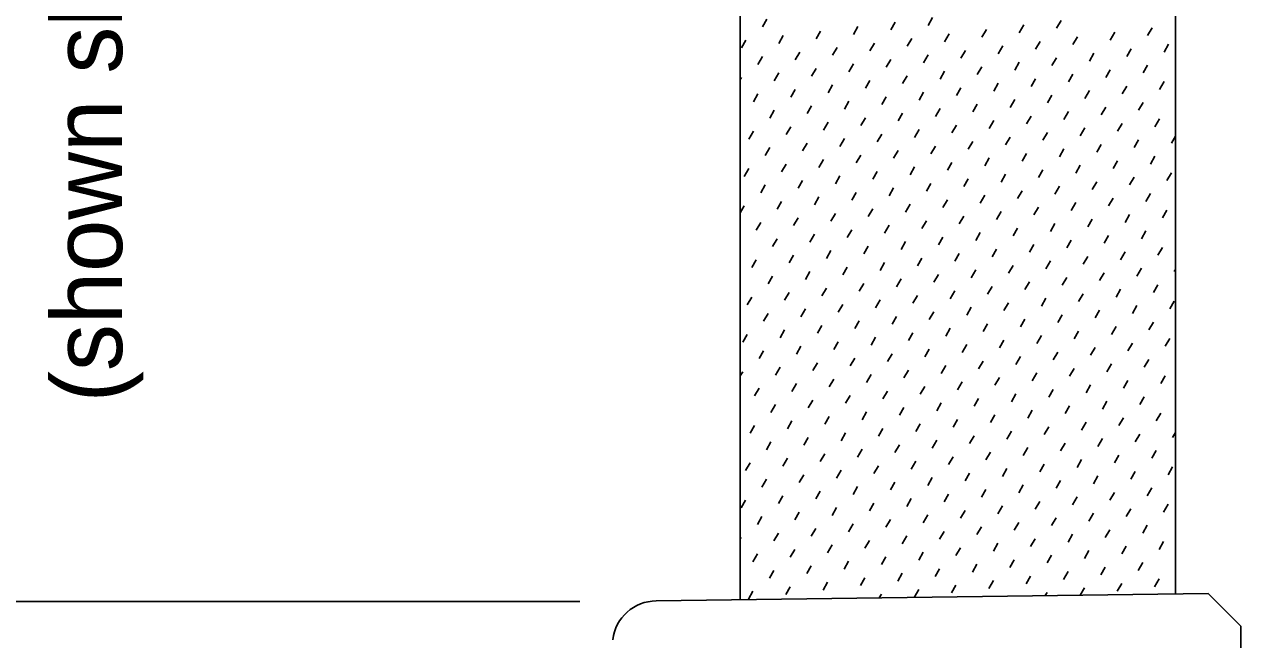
# Model space of a CAD drawing. Extents: x 21629.5 to 21698.8, y 56199.4 to 56237.6.
# Drawn here: x 21644.187 to 21647.681, y 56214.672 to 56216.439 of the extents above; entities that cross this region are included whole.
import ezdxf

# ---------------------------------------------------------------- set-up
doc = ezdxf.new("R2010")
doc.units = 0
for name, color, linetype in [('Dimension', 7, 'Continuous'), ('ExistSuperStruct', 7, 'Continuous'), ('Miscellaneous', 7, 'Continuous')]:
    doc.layers.add(name, color=color, linetype=linetype)

msp = doc.modelspace()

# ---------------------------------------------------------------- linework, layer by layer
at = {"layer": 'Dimension'}
msp.add_line((21645.7831, 56214.7815), (21643.3116, 56214.7815), dxfattribs=at)
at = {"layer": 'ExistSuperStruct'}
for p, q in [((21647.494, 56217.7505), (21647.494, 56214.8034)), ((21646.244, 56214.7863), (21646.244, 56216.5317)), ((21646.0026, 56214.783), (21647.5877, 56214.8047)), ((21647.6815, 56214.711), (21647.5877, 56214.8047)), ((21647.6815, 56212.8767), (21647.6815, 56214.711))]:
    msp.add_line(p, q, dxfattribs=at)
msp.add_arc((21646.0026, 56214.658), 0.125, 90, 173.6598, dxfattribs=at)
at = {"layer": 'Miscellaneous'}
for p, q in [((21646.3075, 56216.4312), (21646.3205, 56216.4536)), ((21646.5691, 56216.41), (21646.5821, 56216.4324)), ((21646.6764, 56216.4229), (21646.6893, 56216.4453)), ((21646.7836, 56216.4359), (21646.7966, 56216.4583)), ((21647.0452, 56216.4147), (21647.0582, 56216.4371)), ((21647.1525, 56216.4276), (21647.1654, 56216.45)), ((21647.4141, 56216.4064), (21647.4271, 56216.4288)), ((21646.2474, 56216.3711), (21646.2603, 56216.3935)), ((21646.3546, 56216.384), (21646.3676, 56216.4064)), ((21646.4619, 56216.397), (21646.4748, 56216.4194)), ((21646.7235, 56216.3758), (21646.7365, 56216.3982)), ((21646.8307, 56216.3888), (21646.8437, 56216.4111)), ((21646.938, 56216.4017), (21646.951, 56216.4241)), ((21647.1996, 56216.3805), (21647.2126, 56216.4029)), ((21647.3069, 56216.3935), (21647.3198, 56216.4159)), ((21646.4018, 56216.3369), (21646.4147, 56216.3593)), ((21646.509, 56216.3499), (21646.522, 56216.3723)), ((21646.6163, 56216.3628), (21646.6292, 56216.3852)), ((21646.8779, 56216.3416), (21646.8909, 56216.364)), ((21646.9851, 56216.3546), (21646.9981, 56216.377)), ((21647.0924, 56216.3675), (21647.1053, 56216.3899)), ((21647.354, 56216.3463), (21647.367, 56216.3687)), ((21647.4613, 56216.3593), (21647.4742, 56216.3817)), ((21646.2945, 56216.3239), (21646.3075, 56216.3463)), ((21646.5562, 56216.3027), (21646.5691, 56216.3251)), ((21646.6634, 56216.3157), (21646.6764, 56216.3381)), ((21646.7706, 56216.3287), (21646.7836, 56216.351)), ((21647.0323, 56216.3074), (21647.0452, 56216.3298)), ((21647.1395, 56216.3204), (21647.1525, 56216.3428)), ((21647.2468, 56216.3334), (21647.2597, 56216.3558)), ((21646.3417, 56216.2768), (21646.3546, 56216.2992)), ((21646.4489, 56216.2898), (21646.4619, 56216.3122)), ((21646.7105, 56216.2685), (21646.7235, 56216.2909)), ((21646.8178, 56216.2815), (21646.8307, 56216.3039)), ((21646.925, 56216.2945), (21646.938, 56216.3169)), ((21647.1867, 56216.2733), (21647.1996, 56216.2957)), ((21647.2939, 56216.2862), (21647.3069, 56216.3086)), ((21647.4011, 56216.2992), (21647.4141, 56216.3216)), ((21646.244, 56216.2804), (21646.2474, 56216.2862)), ((21646.3888, 56216.2297), (21646.4018, 56216.252)), ((21646.4961, 56216.2426), (21646.509, 56216.265)), ((21646.6033, 56216.2556), (21646.6163, 56216.278)), ((21646.8649, 56216.2344), (21646.8779, 56216.2568)), ((21646.9722, 56216.2473), (21646.9851, 56216.2697)), ((21647.0794, 56216.2603), (21647.0924, 56216.2827)), ((21647.341, 56216.2391), (21647.354, 56216.2615)), ((21647.4483, 56216.252), (21647.4613, 56216.2744)), ((21646.2816, 56216.2167), (21646.2945, 56216.2391)), ((21646.5432, 56216.1955), (21646.5562, 56216.2179)), ((21646.6504, 56216.2084), (21646.6634, 56216.2308)), ((21646.7577, 56216.2214), (21646.7706, 56216.2438)), ((21647.0193, 56216.2002), (21647.0323, 56216.2226)), ((21647.1266, 56216.2132), (21647.1395, 56216.2355)), ((21647.2338, 56216.2261), (21647.2468, 56216.2485)), ((21646.3287, 56216.1696), (21646.3417, 56216.1919)), ((21646.4359, 56216.1825), (21646.4489, 56216.2049)), ((21646.6976, 56216.1613), (21646.7105, 56216.1837)), ((21646.8048, 56216.1743), (21646.8178, 56216.1967)), ((21646.9121, 56216.1872), (21646.925, 56216.2096)), ((21647.1737, 56216.166), (21647.1867, 56216.1884)), ((21647.2809, 56216.179), (21647.2939, 56216.2014)), ((21647.3882, 56216.1919), (21647.4011, 56216.2143)), ((21646.4831, 56216.1354), (21646.4961, 56216.1578)), ((21646.5903, 56216.1483), (21646.6033, 56216.1707)), ((21646.852, 56216.1271), (21646.8649, 56216.1495)), ((21646.9592, 56216.1401), (21646.9722, 56216.1625)), ((21647.0665, 56216.1531), (21647.0794, 56216.1754)), ((21647.3281, 56216.1318), (21647.341, 56216.1542)), ((21647.4353, 56216.1448), (21647.4483, 56216.1672)), ((21646.2686, 56216.1094), (21646.2816, 56216.1318)), ((21646.3758, 56216.1224), (21646.3888, 56216.1448)), ((21646.6375, 56216.1012), (21646.6504, 56216.1236)), ((21646.7447, 56216.1142), (21646.7577, 56216.1366)), ((21647.0063, 56216.0929), (21647.0193, 56216.1153)), ((21647.1136, 56216.1059), (21647.1266, 56216.1283)), ((21647.2208, 56216.1189), (21647.2338, 56216.1413)), ((21647.4825, 56216.0977), (21647.494, 56216.1176)), ((21646.3157, 56216.0623), (21646.3287, 56216.0847)), ((21646.423, 56216.0753), (21646.4359, 56216.0977)), ((21646.5302, 56216.0882), (21646.5432, 56216.1106)), ((21646.7919, 56216.067), (21646.8048, 56216.0894)), ((21646.8991, 56216.08), (21646.9121, 56216.1024)), ((21647.1607, 56216.0588), (21647.1737, 56216.0812)), ((21647.268, 56216.0717), (21647.2809, 56216.0941)), ((21647.3752, 56216.0847), (21647.3882, 56216.1071)), ((21646.4701, 56216.0281), (21646.4831, 56216.0505)), ((21646.5774, 56216.0411), (21646.5903, 56216.0635)), ((21646.6846, 56216.0541), (21646.6976, 56216.0765)), ((21646.839, 56216.0199), (21646.852, 56216.0423)), ((21646.9462, 56216.0328), (21646.9592, 56216.0552)), ((21647.0535, 56216.0458), (21647.0665, 56216.0682)), ((21647.3151, 56216.0246), (21647.3281, 56216.047)), ((21647.4224, 56216.0376), (21647.4353, 56216.06)), ((21646.2556, 56216.0022), (21646.2686, 56216.0246)), ((21646.3629, 56216.0152), (21646.3758, 56216.0376)), ((21646.6245, 56215.994), (21646.6375, 56216.0163)), ((21646.7318, 56216.0069), (21646.7447, 56216.0293)), ((21646.9934, 56215.9857), (21647.0063, 56216.0081)), ((21647.1006, 56215.9987), (21647.1136, 56216.0211)), ((21647.2079, 56216.0116), (21647.2208, 56216.034)), ((21647.4695, 56215.9904), (21647.4825, 56216.0128)), ((21646.3028, 56215.9551), (21646.3157, 56215.9775)), ((21646.41, 56215.968), (21646.423, 56215.9904)), ((21646.5173, 56215.981), (21646.5302, 56216.0034)), ((21646.7789, 56215.9598), (21646.7919, 56215.9822)), ((21646.8861, 56215.9727), (21646.8991, 56215.9951)), ((21647.1478, 56215.9515), (21647.1607, 56215.9739)), ((21647.255, 56215.9645), (21647.268, 56215.9869)), ((21647.3623, 56215.9775), (21647.3752, 56215.9998)), ((21646.4572, 56215.9209), (21646.4701, 56215.9433)), ((21646.5644, 56215.9339), (21646.5774, 56215.9562)), ((21646.6716, 56215.9468), (21646.6846, 56215.9692)), ((21646.9333, 56215.9256), (21646.9462, 56215.948)), ((21647.0405, 56215.9386), (21647.0535, 56215.961)), ((21647.3022, 56215.9174), (21647.3151, 56215.9397)), ((21647.4094, 56215.9303), (21647.4224, 56215.9527)), ((21646.244, 56215.8973), (21646.2556, 56215.9174)), ((21646.3499, 56215.9079), (21646.3629, 56215.9303)), ((21646.6115, 56215.8867), (21646.6245, 56215.9091)), ((21646.7188, 56215.8997), (21646.7318, 56215.9221)), ((21646.826, 56215.9126), (21646.839, 56215.935)), ((21647.0877, 56215.8914), (21647.1006, 56215.9138)), ((21647.1949, 56215.9044), (21647.2079, 56215.9268)), ((21647.4565, 56215.8832), (21647.4695, 56215.9056)), ((21646.2898, 56215.8478), (21646.3028, 56215.8702)), ((21646.3971, 56215.8608), (21646.41, 56215.8832)), ((21646.5043, 56215.8737), (21646.5173, 56215.8961)), ((21646.7659, 56215.8525), (21646.7789, 56215.8749)), ((21646.8732, 56215.8655), (21646.8861, 56215.8879)), ((21646.9804, 56215.8785), (21646.9934, 56215.9009)), ((21647.242, 56215.8572), (21647.255, 56215.8796)), ((21647.3493, 56215.8702), (21647.3623, 56215.8926)), ((21646.4442, 56215.8136), (21646.4572, 56215.836)), ((21646.5514, 56215.8266), (21646.5644, 56215.849)), ((21646.6587, 56215.8396), (21646.6716, 56215.862)), ((21646.9203, 56215.8184), (21646.9333, 56215.8407)), ((21647.0276, 56215.8313), (21647.0405, 56215.8537)), ((21647.1348, 56215.8443), (21647.1478, 56215.8667)), ((21647.2892, 56215.8101), (21647.3022, 56215.8325)), ((21647.3964, 56215.8231), (21647.4094, 56215.8455)), ((21646.337, 56215.8007), (21646.3499, 56215.8231)), ((21646.5986, 56215.7795), (21646.6115, 56215.8019)), ((21646.7058, 56215.7924), (21646.7188, 56215.8148)), ((21646.8131, 56215.8054), (21646.826, 56215.8278)), ((21647.0747, 56215.7842), (21647.0877, 56215.8066)), ((21647.1819, 56215.7971), (21647.1949, 56215.8195)), ((21647.4436, 56215.7759), (21647.4565, 56215.7983)), ((21646.2768, 56215.7406), (21646.2898, 56215.763)), ((21646.3841, 56215.7535), (21646.3971, 56215.7759)), ((21646.4913, 56215.7665), (21646.5043, 56215.7889)), ((21646.753, 56215.7453), (21646.7659, 56215.7677)), ((21646.8602, 56215.7583), (21646.8732, 56215.7806)), ((21646.9675, 56215.7712), (21646.9804, 56215.7936)), ((21647.2291, 56215.75), (21647.242, 56215.7724)), ((21647.3363, 56215.763), (21647.3493, 56215.7854)), ((21646.4312, 56215.7064), (21646.4442, 56215.7288)), ((21646.5385, 56215.7194), (21646.5514, 56215.7418)), ((21646.6457, 56215.7323), (21646.6587, 56215.7547)), ((21646.9074, 56215.7111), (21646.9203, 56215.7335)), ((21647.0146, 56215.7241), (21647.0276, 56215.7465)), ((21647.1218, 56215.737), (21647.1348, 56215.7594)), ((21647.3835, 56215.7158), (21647.3964, 56215.7382)), ((21647.4907, 56215.7288), (21647.494, 56215.7345)), ((21646.324, 56215.6934), (21646.337, 56215.7158)), ((21646.5856, 56215.6722), (21646.5986, 56215.6946)), ((21646.6929, 56215.6852), (21646.7058, 56215.7076)), ((21646.8001, 56215.6981), (21646.8131, 56215.7205)), ((21647.0617, 56215.6769), (21647.0747, 56215.6993)), ((21647.169, 56215.6899), (21647.1819, 56215.7123)), ((21647.2762, 56215.7029), (21647.2892, 56215.7253)), ((21646.3711, 56215.6463), (21646.3841, 56215.6687)), ((21646.4784, 56215.6593), (21646.4913, 56215.6816)), ((21646.74, 56215.638), (21646.753, 56215.6604)), ((21646.8472, 56215.651), (21646.8602, 56215.6734)), ((21646.9545, 56215.664), (21646.9675, 56215.6864)), ((21647.2161, 56215.6428), (21647.2291, 56215.6651)), ((21647.3234, 56215.6557), (21647.3363, 56215.6781)), ((21647.4306, 56215.6687), (21647.4436, 56215.6911)), ((21646.2639, 56215.6333), (21646.2768, 56215.6557)), ((21646.5255, 56215.6121), (21646.5385, 56215.6345)), ((21646.6328, 56215.6251), (21646.6457, 56215.6475)), ((21646.8944, 56215.6039), (21646.9074, 56215.6263)), ((21647.0016, 56215.6168), (21647.0146, 56215.6392)), ((21647.1089, 56215.6298), (21647.1218, 56215.6522)), ((21647.3705, 56215.6086), (21647.3835, 56215.631)), ((21647.4778, 56215.6215), (21647.4907, 56215.6439)), ((21646.311, 56215.5862), (21646.324, 56215.6086)), ((21646.4183, 56215.5992), (21646.4312, 56215.6215)), ((21646.6799, 56215.5779), (21646.6929, 56215.6003)), ((21646.7871, 56215.5909), (21646.8001, 56215.6133)), ((21647.0488, 56215.5697), (21647.0617, 56215.5921)), ((21647.156, 56215.5827), (21647.169, 56215.605)), ((21647.2633, 56215.5956), (21647.2762, 56215.618)), ((21646.3582, 56215.539), (21646.3711, 56215.5614)), ((21646.4654, 56215.552), (21646.4784, 56215.5744)), ((21646.5727, 56215.565), (21646.5856, 56215.5874)), ((21646.727, 56215.5308), (21646.74, 56215.5532)), ((21646.8343, 56215.5438), (21646.8472, 56215.5662)), ((21646.9415, 56215.5567), (21646.9545, 56215.5791)), ((21647.2032, 56215.5355), (21647.2161, 56215.5579)), ((21647.3104, 56215.5485), (21647.3234, 56215.5709)), ((21647.4176, 56215.5614), (21647.4306, 56215.5838)), ((21646.2509, 56215.5261), (21646.2639, 56215.5485)), ((21646.5125, 56215.5049), (21646.5255, 56215.5273)), ((21646.6198, 56215.5178), (21646.6328, 56215.5402)), ((21646.8814, 56215.4966), (21646.8944, 56215.519)), ((21646.9887, 56215.5096), (21647.0016, 56215.532)), ((21647.0959, 56215.5225), (21647.1089, 56215.5449)), ((21647.3575, 56215.5013), (21647.3705, 56215.5237)), ((21647.4648, 56215.5143), (21647.4778, 56215.5367)), ((21646.2981, 56215.4789), (21646.311, 56215.5013)), ((21646.4053, 56215.4919), (21646.4183, 56215.5143)), ((21646.6669, 56215.4707), (21646.6799, 56215.4931)), ((21646.7742, 56215.4837), (21646.7871, 56215.5061)), ((21647.0358, 56215.4624), (21647.0488, 56215.4848)), ((21647.1431, 56215.4754), (21647.156, 56215.4978)), ((21647.2503, 56215.4884), (21647.2633, 56215.5108)), ((21646.3452, 56215.4318), (21646.3582, 56215.4542)), ((21646.4524, 56215.4448), (21646.4654, 56215.4672)), ((21646.5597, 56215.4577), (21646.5727, 56215.4801)), ((21646.8213, 56215.4365), (21646.8343, 56215.4589)), ((21646.9286, 56215.4495), (21646.9415, 56215.4719)), ((21647.1902, 56215.4283), (21647.2032, 56215.4507)), ((21647.2974, 56215.4412), (21647.3104, 56215.4636)), ((21647.4047, 56215.4542), (21647.4176, 56215.4766)), ((21646.244, 56215.4293), (21646.2509, 56215.4412)), ((21646.4996, 56215.3976), (21646.5125, 56215.42)), ((21646.6068, 56215.4106), (21646.6198, 56215.433)), ((21646.7141, 56215.4236), (21646.727, 56215.4459)), ((21646.9757, 56215.4023), (21646.9887, 56215.4247)), ((21647.0829, 56215.4153), (21647.0959, 56215.4377)), ((21647.3446, 56215.3941), (21647.3575, 56215.4165)), ((21647.4518, 56215.4071), (21647.4648, 56215.4294)), ((21646.2851, 56215.3717), (21646.2981, 56215.3941)), ((21646.3923, 56215.3847), (21646.4053, 56215.4071)), ((21646.654, 56215.3635), (21646.6669, 56215.3858)), ((21646.7612, 56215.3764), (21646.7742, 56215.3988)), ((21646.8685, 56215.3894), (21646.8814, 56215.4118)), ((21647.1301, 56215.3682), (21647.1431, 56215.3906)), ((21647.2373, 56215.3811), (21647.2503, 56215.4035)), ((21646.3322, 56215.3246), (21646.3452, 56215.347)), ((21646.4395, 56215.3375), (21646.4524, 56215.3599)), ((21646.5467, 56215.3505), (21646.5597, 56215.3729)), ((21646.8084, 56215.3293), (21646.8213, 56215.3517)), ((21646.9156, 56215.3422), (21646.9286, 56215.3646)), ((21647.0228, 56215.3552), (21647.0358, 56215.3776)), ((21647.1772, 56215.321), (21647.1902, 56215.3434)), ((21647.2845, 56215.334), (21647.2974, 56215.3564)), ((21647.3917, 56215.347), (21647.4047, 56215.3693)), ((21646.4866, 56215.2904), (21646.4996, 56215.3128)), ((21646.5939, 56215.3033), (21646.6068, 56215.3257)), ((21646.7011, 56215.3163), (21646.7141, 56215.3387)), ((21646.9627, 56215.2951), (21646.9757, 56215.3175)), ((21647.07, 56215.3081), (21647.0829, 56215.3305)), ((21647.3316, 56215.2868), (21647.3446, 56215.3092)), ((21647.4389, 56215.2998), (21647.4518, 56215.3222)), ((21646.2721, 56215.2645), (21646.2851, 56215.2868)), ((21646.3794, 56215.2774), (21646.3923, 56215.2998)), ((21646.641, 56215.2562), (21646.654, 56215.2786)), ((21646.7483, 56215.2692), (21646.7612, 56215.2916)), ((21646.8555, 56215.2821), (21646.8685, 56215.3045)), ((21647.1171, 56215.2609), (21647.1301, 56215.2833)), ((21647.2244, 56215.2739), (21647.2373, 56215.2963)), ((21646.3193, 56215.2173), (21646.3322, 56215.2397)), ((21646.4265, 56215.2303), (21646.4395, 56215.2527)), ((21646.5338, 56215.2432), (21646.5467, 56215.2656)), ((21646.7954, 56215.222), (21646.8084, 56215.2444)), ((21646.9026, 56215.235), (21646.9156, 56215.2574)), ((21647.0099, 56215.248), (21647.0228, 56215.2703)), ((21647.2715, 56215.2267), (21647.2845, 56215.2491)), ((21647.3788, 56215.2397), (21647.3917, 56215.2621)), ((21647.486, 56215.2527), (21647.494, 56215.2665)), ((21646.4737, 56215.1831), (21646.4866, 56215.2055)), ((21646.5809, 56215.1961), (21646.5939, 56215.2185)), ((21646.6881, 56215.2091), (21646.7011, 56215.2315)), ((21646.9498, 56215.1879), (21646.9627, 56215.2102)), ((21647.057, 56215.2008), (21647.07, 56215.2232)), ((21647.1643, 56215.2138), (21647.1772, 56215.2362)), ((21647.4259, 56215.1926), (21647.4389, 56215.215)), ((21646.2592, 56215.1572), (21646.2721, 56215.1796)), ((21646.3664, 56215.1702), (21646.3794, 56215.1926)), ((21646.628, 56215.149), (21646.641, 56215.1714)), ((21646.7353, 56215.1619), (21646.7483, 56215.1843)), ((21646.8425, 56215.1749), (21646.8555, 56215.1973)), ((21647.1042, 56215.1537), (21647.1171, 56215.1761)), ((21647.2114, 56215.1666), (21647.2244, 56215.189)), ((21647.3187, 56215.1796), (21647.3316, 56215.202)), ((21646.4136, 56215.123), (21646.4265, 56215.1454)), ((21646.5208, 56215.136), (21646.5338, 56215.1584)), ((21646.7824, 56215.1148), (21646.7954, 56215.1372)), ((21646.8897, 56215.1277), (21646.9026, 56215.1501)), ((21646.9969, 56215.1407), (21647.0099, 56215.1631)), ((21647.2585, 56215.1195), (21647.2715, 56215.1419)), ((21647.3658, 56215.1325), (21647.3788, 56215.1549)), ((21647.473, 56215.1454), (21647.486, 56215.1678)), ((21646.3063, 56215.1101), (21646.3193, 56215.1325)), ((21646.5679, 56215.0889), (21646.5809, 56215.1112)), ((21646.6752, 56215.1018), (21646.6881, 56215.1242)), ((21646.9368, 56215.0806), (21646.9498, 56215.103)), ((21647.0441, 56215.0936), (21647.057, 56215.116)), ((21647.1513, 56215.1065), (21647.1643, 56215.1289)), ((21647.4129, 56215.0853), (21647.4259, 56215.1077)), ((21646.2462, 56215.05), (21646.2592, 56215.0724)), ((21646.3535, 56215.0629), (21646.3664, 56215.0853)), ((21646.4607, 56215.0759), (21646.4737, 56215.0983)), ((21646.6151, 56215.0417), (21646.628, 56215.0641)), ((21646.7223, 56215.0547), (21646.7353, 56215.0771)), ((21646.8296, 56215.0676), (21646.8425, 56215.09)), ((21647.0912, 56215.0464), (21647.1042, 56215.0688)), ((21647.1984, 56215.0594), (21647.2114, 56215.0818)), ((21647.3057, 56215.0724), (21647.3187, 56215.0948)), ((21646.4006, 56215.0158), (21646.4136, 56215.0382)), ((21646.5078, 56215.0288), (21646.5208, 56215.0511)), ((21646.7695, 56215.0075), (21646.7824, 56215.0299)), ((21646.8767, 56215.0205), (21646.8897, 56215.0429)), ((21646.984, 56215.0335), (21646.9969, 56215.0559)), ((21647.2456, 56215.0123), (21647.2585, 56215.0346)), ((21647.3528, 56215.0252), (21647.3658, 56215.0476)), ((21647.4601, 56215.0382), (21647.473, 56215.0606)), ((21646.2933, 56215.0028), (21646.3063, 56215.0252)), ((21646.555, 56214.9816), (21646.5679, 56215.004)), ((21646.6622, 56214.9946), (21646.6752, 56215.017)), ((21646.9239, 56214.9734), (21646.9368, 56214.9958)), ((21647.0311, 56214.9863), (21647.0441, 56215.0087)), ((21647.1383, 56214.9993), (21647.1513, 56215.0217)), ((21647.4, 56214.9781), (21647.4129, 56215.0005)), ((21646.244, 56214.9613), (21646.2462, 56214.9651)), ((21646.3405, 56214.9557), (21646.3535, 56214.9781)), ((21646.4477, 56214.9686), (21646.4607, 56214.991)), ((21646.7094, 56214.9474), (21646.7223, 56214.9698)), ((21646.8166, 56214.9604), (21646.8296, 56214.9828)), ((21647.0782, 56214.9392), (21647.0912, 56214.9616)), ((21647.1855, 56214.9522), (21647.1984, 56214.9745)), ((21647.2927, 56214.9651), (21647.3057, 56214.9875)), ((21646.3876, 56214.9085), (21646.4006, 56214.9309)), ((21646.4949, 56214.9215), (21646.5078, 56214.9439)), ((21646.6021, 56214.9345), (21646.6151, 56214.9569)), ((21646.8637, 56214.9133), (21646.8767, 56214.9357)), ((21646.971, 56214.9262), (21646.984, 56214.9486)), ((21647.2326, 56214.905), (21647.2456, 56214.9274)), ((21647.3399, 56214.918), (21647.3528, 56214.9404)), ((21647.4471, 56214.9309), (21647.4601, 56214.9533)), ((21646.2804, 56214.8956), (21646.2933, 56214.918)), ((21646.542, 56214.8744), (21646.555, 56214.8968)), ((21646.6493, 56214.8873), (21646.6622, 56214.9097)), ((21646.7565, 56214.9003), (21646.7695, 56214.9227)), ((21647.0181, 56214.8791), (21647.0311, 56214.9015)), ((21647.1254, 56214.892), (21647.1383, 56214.9144)), ((21647.387, 56214.8708), (21647.4, 56214.8932)), ((21646.3275, 56214.8484), (21646.3405, 56214.8708)), ((21646.4348, 56214.8614), (21646.4477, 56214.8838)), ((21646.6964, 56214.8402), (21646.7094, 56214.8626)), ((21646.8036, 56214.8532), (21646.8166, 56214.8755)), ((21646.9109, 56214.8661), (21646.9239, 56214.8885)), ((21647.0653, 56214.8319), (21647.0782, 56214.8543)), ((21647.1725, 56214.8449), (21647.1855, 56214.8673)), ((21647.2798, 56214.8579), (21647.2927, 56214.8803)), ((21646.3747, 56214.8013), (21646.3876, 56214.8237)), ((21646.4819, 56214.8143), (21646.4949, 56214.8367)), ((21646.5892, 56214.8272), (21646.6021, 56214.8496)), ((21646.8508, 56214.806), (21646.8637, 56214.8284)), ((21646.958, 56214.819), (21646.971, 56214.8414)), ((21647.2208, 56214.7997), (21647.2326, 56214.8202)), ((21647.3269, 56214.8107), (21647.3399, 56214.8331)), ((21647.4341, 56214.8237), (21647.4471, 56214.8461)), ((21646.2674, 56214.7883), (21646.2804, 56214.8107)), ((21646.6431, 56214.7918), (21646.6493, 56214.8025)), ((21646.7436, 56214.7932), (21646.7565, 56214.8154)), ((21647.1202, 56214.7983), (21647.1254, 56214.8072))]:
    msp.add_line(p, q, dxfattribs=at)

# ---------------------------------------------------------------- texts
at = {"layer": 'Dimension'}
msp.add_text('(shown shaded)', height=0.2016, rotation=90, dxfattribs=at).set_placement((21644.4681, 56215.3533))

doc.saveas('drawing.dxf')
